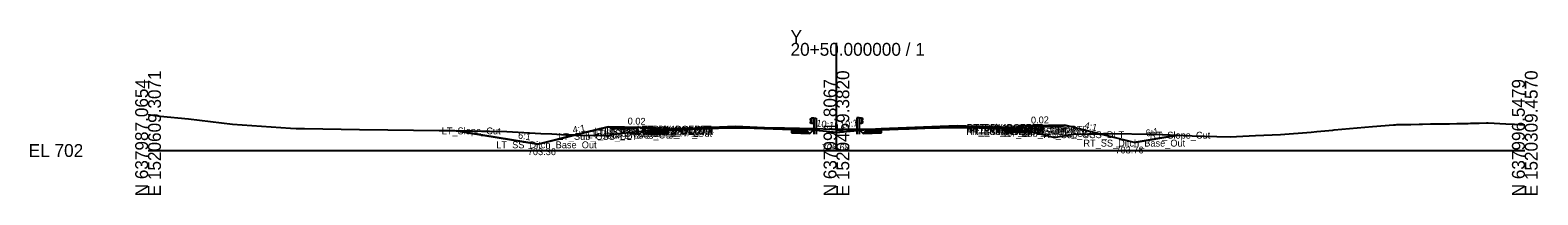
# Model space of a CAD drawing. Extents: x -26 to 303, y -10 to 5039.
# Drawn here: x -25.7 to 302.8, y 3990.3 to 4026.3 of the extents above; entities that cross this region are included whole.
import ezdxf

# ---------------------------------------------------------------- set-up
doc = ezdxf.new("R2010")
doc.units = 0
for name, color, linetype in [('Default', 7, 'Continuous'), ('Exist Cross Section Cell', 7, 'Continuous'), ('Exist XS Center Line Elevation Label', 7, 'Continuous'), ('Exist XS Ground Line', 7, 'Continuous'), ('Prop CMT Pvmt Course 1', 7, 'Continuous'), ('Prop CMT Pvmt Course 2', 7, 'Continuous'), ('Prop CMT Pvmt Course 3', 7, 'Continuous'), ('Prop CMT Pvmt Surface Shoulder', 7, 'Continuous'), ('Prop CMT Shld Paved Course 1', 7, 'Continuous'), ('Prop CMT Shld Paved Course 2', 7, 'Continuous'), ('Prop CMT Shld Paved Course 3', 7, 'Continuous'), ('Prop CMT Slope Grass', 7, 'Continuous'), ('Prop CMT Subgrade Earthwork', 7, 'Continuous'), ('Prop Conc 4in Sidewalk', 7, 'Continuous'), ('Prop XS Ditch Standard Text', 7, 'Continuous'), ('Prop XS Earthwork Shape', 7, 'Continuous'), ('Prop XS Side Slope Text', 7, 'Continuous'), ('Scratch_Level_0', 7, 'Continuous'), ('Typical Curb CELL', 7, 'Continuous'), ('Typical Guardrail CELL', 7, 'Continuous'), ('Typical Shoulder Slope Information CELL', 7, 'Continuous')]:
    doc.layers.add(name, color=color, linetype=linetype)

# ---------------------------------------------------------------- blocks, each defined once
blk = doc.blocks.new('2_6 CURB RIGHT')
at = {"layer": 'Typical Curb CELL'}
for p, q in [((0, -0.58), (0, 0)), ((0, 0), (1.75, -0.07)), ((2, 0.17), (2, 0.18)), ((2.5, 0.42), (2.24, 0.42)), ((2.31, 0.08), (2.33, -0.01)), ((2.46, 0.04), (2.31, 0.08)), ((2.33, -0.01), (2.46, 0.04)), ((2.5, -0.58), (2.5, 0.42)), ((2.5, -0.58), (0, -0.58)), ((0.26, -0.34), (0.35, -0.22)), ((0.38, -0.34), (0.26, -0.34)), ((0.35, -0.22), (0.38, -0.34)), ((1.03, -0.39), (1.09, -0.28)), ((1.19, -0.36), (1.03, -0.39)), ((1.09, -0.28), (1.19, -0.36)), ((1.51, -0.34), (1.6, -0.22)), ((1.63, -0.34), (1.51, -0.34)), ((1.6, -0.22), (1.63, -0.34)), ((2.27, -0.39), (2.34, -0.28)), ((2.44, -0.36), (2.27, -0.39)), ((2.34, -0.28), (2.44, -0.36))]:
    blk.add_line(p, q, dxfattribs=at)
for centre in [(2.27, 0.34), (2.43, 0.12), (2.49, 0.31), (0.01, -0.55), (0.02, -0.25), (0.03, -0.15), (0.07, -0.39), (0.09, -0.18), (0.17, -0.34), (0.2, -0.06), (0.22, -0.58), (0.3, -0.14), (0.34, -0.04), (0.38, -0.51), (0.49, -0.1), (0.52, -0.21), (0.59, -0.53), (0.67, -0.29), (0.69, -0.12), (0.7, -0.45), (0.71, -0.07), (0.76, -0.56), (0.79, -0.26), (0.93, -0.5), (0.97, -0.1), (1.09, -0.15), (1.11, -0.54), (1.26, -0.55), (1.27, -0.25), (1.28, -0.15), (1.32, -0.39), (1.34, -0.18), (1.42, -0.34), (1.45, -0.1), (1.47, -0.58), (1.54, -0.14), (1.63, -0.51), (1.74, -0.1), (1.77, -0.21), (1.84, -0.53), (1.92, -0.29), (1.94, -0.12), (1.95, -0.45), (1.96, -0.07), (2.01, -0.56), (2.04, -0.26), (2.18, -0.5), (2.22, -0.1), (2.34, -0.15), (2.35, -0.54)]:
    blk.add_circle(centre, 0.00802, dxfattribs=at)
for centre, start, end in [((1.76, 0.17), 267.6155, 0), ((2.24, 0.18), 90, 180)]:
    blk.add_arc(centre, 0.24, start, end, dxfattribs=at)

msp = doc.modelspace()

# ---------------------------------------------------------------- linework, layer by layer
at = {"layer": 'Exist Cross Section Cell'}
for p, q in [((150, 4000), (150, 4023.49)), ((0, 4000), (150, 4000)), ((150, 4000), (300, 4000))]:
    msp.add_line(p, q, dxfattribs=at)
at = {"layer": 'Exist XS Ground Line'}
msp.add_lwpolyline([(0, 4007.83), (2.65, 4007.47), (8.82, 4006.91), (18.4, 4005.77), (31.03, 4004.88), (32.29, 4004.83), (34.06, 4004.82), (46.09, 4004.6), (52.24, 4004.48), (63.44, 4004.38), (65.08, 4004.36), (65.85, 4004.35), (66.86, 4004.34), (78.21, 4004.14), (85.59, 4003.75), (87.97, 4003.66), (91.17, 4003.44), (94.16, 4003.35), (99.49, 4003.28), (100.04, 4003.28), (100.4, 4003.33), (102.19, 4003.61), (105.36, 4003.99), (106.12, 4004.06), (111.26, 4004.59), (112.28, 4004.58), (114.36, 4004.66), (116.71, 4004.72), (119.22, 4004.78), (121.72, 4004.85), (124.22, 4004.91), (125, 4004.94), (126.18, 4004.97), (126.72, 4004.97), (127.07, 4004.97), (129.21, 4004.97), (131.22, 4004.98), (131.7, 4004.98), (133.64, 4004.97), (134.21, 4004.97), (134.8, 4004.97), (136.73, 4004.96), (137.46, 4004.95), (138.15, 4004.95), (138.7, 4004.94), (141.96, 4004.87), (145.4, 4004.79), (148.89, 4004.69), (150, 4004.68), (152.34, 4004.66), (158.87, 4004.69), (160.57, 4004.68), (162.53, 4004.66), (164.26, 4004.71), (165.85, 4004.76), (166.76, 4004.78), (167.62, 4004.81), (169.25, 4004.87), (170.98, 4004.92), (171.73, 4004.94), (172.45, 4004.96), (174.53, 4005.04), (176.12, 4005.02), (176.73, 4005.02), (178.7, 4005.03), (179.22, 4005.03), (181.3, 4005.02), (181.73, 4005.02), (183.92, 4005.01), (184.26, 4005.01), (185.48, 4005.01), (186.05, 4005.01), (186.52, 4004.95), (188.98, 4004.75), (190.2, 4004.55), (192.8, 4004.02), (196.34, 4003.14), (197.52, 4002.85), (198.57, 4003.03), (201.65, 4003.56), (208.21, 4003.69), (209.22, 4003.69), (219.44, 4003.59), (225.64, 4003.27), (226.31, 4003.25), (227.52, 4003.22), (232.88, 4003.04), (235.76, 4002.98), (241.31, 4003.25), (246.78, 4003.52), (253.43, 4004.04), (254.69, 4004.15), (258.15, 4004.46), (258.45, 4004.49), (266.79, 4005.22), (271.42, 4005.63), (271.83, 4005.64), (272.14, 4005.65), (272.72, 4005.67), (274.38, 4005.7), (275.19, 4005.71), (277, 4005.75), (277.69, 4005.77), (279.42, 4005.8), (280.17, 4005.81), (281.85, 4005.83), (282.68, 4005.85), (283.56, 4005.86), (285.18, 4005.89), (286.14, 4005.91), (287.67, 4005.93), (288.17, 4005.95), (289.48, 4005.98), (290.02, 4005.98), (291.64, 4006.02), (292.01, 4006.01), (295.9, 4005.82), (297.7, 4005.74), (300, 4005.6)], dxfattribs=at)
at = {"layer": 'Prop CMT Pvmt Course 1'}
for points in [[(186.74, 4004.73), (186.74, 4004.98)], [(113.26, 4004.62), (113.26, 4004.37)], [(113.26, 4004.37), (113.27, 4004.37)], [(113.27, 4004.37), (113.27, 4004.62)], [(140.26, 4004.48), (140.26, 4004.73)], [(159.74, 4004.73), (159.74, 4004.48)], [(159.74, 4004.48), (159.75, 4004.48)], [(159.75, 4004.48), (159.75, 4004.73)], [(159.75, 4004.48), (159.75, 4004.73)]]:
    msp.add_lwpolyline(points, dxfattribs=at)
at = {"layer": 'Prop CMT Pvmt Course 2'}
for points in [[(113.27, 4004.37), (113.26, 4004.37)], [(113.26, 4004.37), (113.26, 4004.12)], [(113.26, 4004.12), (113.27, 4004.12)], [(113.27, 4004.12), (113.27, 4004.37)], [(140.26, 4004.23), (140.26, 4004.48)], [(159.75, 4004.48), (159.74, 4004.48)], [(159.74, 4004.48), (159.74, 4004.23)], [(159.74, 4004.23), (159.75, 4004.23)], [(159.75, 4004.23), (159.75, 4004.48)], [(159.75, 4004.23), (159.75, 4004.48)]]:
    msp.add_lwpolyline(points, dxfattribs=at)
at = {"layer": 'Prop CMT Pvmt Course 3'}
for points in [[(113.27, 4004.12), (113.26, 4004.12)], [(113.26, 4004.12), (113.26, 4003.75)], [(113.26, 4003.75), (113.27, 4003.75)], [(113.27, 4003.75), (113.27, 4004.12)], [(140.26, 4003.86), (140.26, 4004.23)], [(140.27, 4003.86), (140.26, 4003.86)], [(159.75, 4004.23), (159.74, 4004.23)], [(159.74, 4004.23), (159.74, 4003.86)], [(159.74, 4003.86), (159.75, 4003.86)], [(159.74, 4003.86), (159.75, 4003.86)], [(159.75, 4003.86), (159.75, 4004.23)], [(159.75, 4003.86), (159.75, 4004.23)]]:
    msp.add_lwpolyline(points, dxfattribs=at)
at = {"layer": 'Prop CMT Pvmt Surface Shoulder'}
for points in [[(128, 4005.22), (112.26, 4004.57)], [(128, 4005.22), (143.26, 4004.61)], [(176.31, 4005.39), (156.75, 4004.61)], [(176.31, 4005.39), (187.75, 4004.94)]]:
    msp.add_lwpolyline(points, dxfattribs=at)
at = {"layer": 'Prop CMT Shld Paved Course 1'}
for p, q in [((128, 4004.97), (113.27, 4004.37)), ((176.3, 4005.14), (187.74, 4004.69))]:
    msp.add_line(p, q, dxfattribs=at)
for points in [[(140.26, 4004.48), (128, 4004.97)], [(159.77, 4004.48), (176.3, 4005.14)], [(112.26, 4004.33), (113.27, 4004.37)], [(113.26, 4004.37), (113.26, 4004.62)], [(159.74, 4004.48), (159.74, 4004.73)], [(187.75, 4004.69), (186.74, 4004.73)]]:
    msp.add_lwpolyline(points, dxfattribs=at)
at = {"layer": 'Prop CMT Shld Paved Course 2'}
for p, q in [((143.78, 4004.09), (143.52, 4004.35)), ((156.23, 4004.09), (156.49, 4004.35))]:
    msp.add_line(p, q, dxfattribs=at)
for points in [[(113.27, 4004.37), (112.26, 4004.33)], [(112.26, 4004.08), (113.27, 4004.12)], [(113.26, 4004.12), (113.26, 4004.37)], [(140.26, 4004.48), (143.52, 4004.35)], [(143.78, 4004.09), (140.26, 4004.23)], [(156.23, 4004.09), (159.75, 4004.23)], [(159.75, 4004.48), (156.49, 4004.35)], [(157.24, 4004.13), (159.76, 4004.23)], [(159.74, 4004.23), (159.74, 4004.48)], [(186.74, 4004.73), (187.75, 4004.69)], [(187.75, 4004.44), (186.74, 4004.48)]]:
    msp.add_lwpolyline(points, dxfattribs=at)
at = {"layer": 'Prop CMT Shld Paved Course 3'}
for p, q in [((109.26, 4004), (108.83, 4003.57)), ((109.76, 4004), (109.26, 4004)), ((144.17, 4003.7), (143.78, 4004.09)), ((155.84, 4003.7), (156.23, 4004.09)), ((190.25, 4004.35), (190.75, 4004.35)), ((190.75, 4004.35), (191.18, 4003.92))]:
    msp.add_line(p, q, dxfattribs=at)
for points in [[(108.83, 4003.57), (113.27, 4003.75)], [(113.27, 4004.12), (112.26, 4004.08)], [(113.26, 4003.75), (113.26, 4004.12)], [(140.26, 4004.23), (143.78, 4004.09)], [(144.17, 4003.7), (140.26, 4003.86)], [(155.84, 4003.7), (159.75, 4003.86)], [(159.75, 4004.23), (156.23, 4004.09)], [(159.74, 4003.86), (159.74, 4004.23)], [(186.74, 4004.48), (187.75, 4004.44)], [(191.18, 4003.92), (186.74, 4004.1)]]:
    msp.add_lwpolyline(points, dxfattribs=at)
at = {"layer": 'Prop CMT Slope Grass'}
for p, q in [((84.98, 4001.36), (100.26, 4005.18)), ((100.26, 4005.18), (109.76, 4004.99)), ((199.75, 4005.54), (190.25, 4005.35)), ((214.9, 4001.75), (199.75, 4005.54)), ((67.13, 4004.33), (84.98, 4001.36)), ((150.01, 4003.94), (143.26, 4004.61)), ((150.01, 4003.94), (156.75, 4004.61))]:
    msp.add_line(p, q, dxfattribs=at)
msp.add_lwpolyline([(214.9, 4001.75), (224.38, 4003.34)], dxfattribs=at)
at = {"layer": 'Prop CMT Subgrade Earthwork'}
for p, q in [((108.83, 4003.57), (107.36, 4005.05)), ((186.74, 4004.1), (186.74, 4004.98)), ((191.18, 4003.92), (192.65, 4005.4)), ((113.27, 4003.75), (113.27, 4004.62)), ((140.26, 4004.73), (140.26, 4003.86)), ((159.75, 4004.73), (159.75, 4003.86))]:
    msp.add_line(p, q, dxfattribs=at)
for points in [[(113.27, 4003.75), (108.83, 4003.57)], [(140.26, 4004.73), (140.26, 4003.86), (140.27, 4003.86)], [(140.26, 4003.86), (144.17, 4003.7)], [(144.17, 4003.7), (144.92, 4004.45)], [(155.84, 4003.7), (155.09, 4004.45)], [(159.75, 4003.86), (155.84, 4003.7)], [(186.74, 4004.1), (191.18, 4003.92)]]:
    msp.add_lwpolyline(points, dxfattribs=at)
at = {"layer": 'Prop Conc 4in Sidewalk'}
for p, q in [((100.76, 4005.17), (100.76, 4004.84)), ((100.76, 4004.84), (105.76, 4004.74)), ((105.76, 4005.07), (105.76, 4004.74)), ((194.25, 4005.43), (194.25, 4005.1)), ((199.25, 4005.2), (194.25, 4005.1)), ((199.25, 4005.53), (199.25, 4005.2))]:
    msp.add_line(p, q, dxfattribs=at)
at = {"layer": 'Prop XS Earthwork Shape'}
for points in [[(100.04, 4003.28), (100.4, 4003.33), (102.19, 4003.61), (105.36, 4003.99), (106.12, 4004.06), (108.13, 4004.27), (107.36, 4005.04), (100.26, 4005.18), (93.08, 4003.39), (94.16, 4003.35), (99.49, 4003.28)], [(125, 4004.94), (126.18, 4004.97), (126.72, 4004.97), (127.07, 4004.97), (129.21, 4004.97), (131.22, 4004.98), (131.7, 4004.98), (133.64, 4004.97), (134.21, 4004.97), (134.3, 4004.97), (128, 4005.22), (114.36, 4004.66), (116.71, 4004.72), (119.22, 4004.78), (121.72, 4004.85), (124.22, 4004.91)], [(134.8, 4004.97), (136.73, 4004.96), (137.46, 4004.95), (138.15, 4004.95), (138.7, 4004.94), (141.96, 4004.87), (145.4, 4004.79), (148.89, 4004.69), (150, 4004.68), (152.34, 4004.66), (158.78, 4004.69), (156.75, 4004.61), (155.09, 4004.45), (150.01, 4003.94), (144.92, 4004.45), (143.26, 4004.61), (140.26, 4004.73), (134.3, 4004.97)], [(169.25, 4004.87), (170.98, 4004.92), (171.73, 4004.94), (172.45, 4004.96), (174.53, 4005.04), (176.12, 4005.02), (176.73, 4005.02), (178.7, 4005.03), (179.22, 4005.03), (181.3, 4005.02), (181.73, 4005.02), (183.92, 4005.01), (184.26, 4005.01), (185.48, 4005.01), (186.01, 4005.01), (176.31, 4005.39), (159.75, 4004.73), (159.75, 4004.69), (160.57, 4004.68), (162.53, 4004.66), (164.26, 4004.71), (165.85, 4004.76), (166.76, 4004.78), (167.62, 4004.81)], [(186.07, 4005), (186.74, 4004.98), (186.74, 4004.94), (186.52, 4004.95)], [(191.18, 4003.92), (191.53, 4004.28), (190.2, 4004.55), (188.98, 4004.75), (186.74, 4004.94), (186.74, 4004.1)], [(191.53, 4004.28), (192.8, 4004.02), (196.34, 4003.14), (197.52, 4002.85), (198.57, 4003.03), (201.65, 4003.56), (207.25, 4003.67), (199.75, 4005.54), (192.65, 4005.4)], [(91.17, 4003.44), (93.08, 4003.39), (84.98, 4001.36), (67.13, 4004.33), (78.21, 4004.14), (85.59, 4003.75), (87.97, 4003.66)], [(108.83, 4003.57), (108.13, 4004.27), (111.26, 4004.59), (112.21, 4004.58), (112.26, 4004.57), (113.27, 4004.62), (113.27, 4003.75)], [(112.21, 4004.58), (112.26, 4004.57), (113.27, 4004.62), (112.28, 4004.58)], [(140.27, 4003.86), (144.17, 4003.7), (144.92, 4004.45), (143.26, 4004.61), (140.26, 4004.73)], [(159.75, 4004.69), (159.75, 4003.86), (155.84, 4003.7), (155.09, 4004.45), (156.75, 4004.61), (158.78, 4004.69), (158.87, 4004.69)], [(207.25, 4003.67), (208.21, 4003.69), (209.22, 4003.69), (219.44, 4003.59), (224.38, 4003.34), (214.9, 4001.75)]]:
    msp.add_lwpolyline(points, close=True, dxfattribs=at)
at = {"layer": 'Typical Guardrail CELL'}
for p, q in [((144.57, 4007.06), (144.28, 4006.85)), ((144.57, 4006.52), (144.28, 4006.73)), ((144.57, 4006.43), (144.28, 4006.23)), ((144.57, 4005.9), (144.28, 4006.1)), ((145.07, 4007.06), (144.57, 4007.06)), ((144.57, 4007.06), (144.57, 4005.9)), ((144.57, 4006.48), (144.57, 4006.52)), ((144.57, 4006.48), (144.57, 4006.43)), ((145.07, 4005.9), (144.57, 4005.9)), ((145.07, 4007.06), (145.07, 4004.57)), ((145.07, 4007.06), (145.57, 4007.06)), ((145.57, 4007.06), (145.57, 4004.57)), ((154.93, 4007.1), (154.43, 4007.1)), ((154.43, 4007.1), (154.43, 4004.61)), ((154.93, 4007.1), (154.93, 4004.61)), ((154.93, 4007.1), (155.43, 4007.1)), ((154.93, 4005.94), (155.43, 4005.94)), ((155.43, 4007.1), (155.43, 4005.94)), ((155.43, 4007.1), (155.72, 4006.89)), ((155.43, 4006.56), (155.72, 4006.77)), ((155.43, 4006.52), (155.43, 4006.56)), ((155.43, 4006.52), (155.43, 4006.47)), ((155.43, 4006.47), (155.72, 4006.27)), ((155.43, 4005.94), (155.72, 4006.14)), ((145.07, 4004.57), (145.57, 4004.57)), ((145.07, 4004.57), (145.07, 4003.56)), ((145.57, 4004.57), (145.57, 4003.56)), ((154.93, 4004.61), (154.43, 4004.61)), ((154.43, 4004.61), (154.43, 4003.6)), ((154.93, 4004.61), (154.93, 4003.6))]:
    msp.add_line(p, q, dxfattribs=at)
for centre, start, end in [((144.33, 4006.79), 125.003, 235.0112), ((144.33, 4006.16), 125.0059, 235.0366), ((155.67, 4006.83), 304.9888, 54.997), ((155.67, 4006.2), 304.9634, 54.9941)]:
    msp.add_arc(centre, 0.0776, start, end, dxfattribs=at)

# ---------------------------------------------------------------- block references
at = {"layer": 'Prop CMT Slope Grass', "yscale": -1, "rotation": 180}
msp.add_blockref('2_6 CURB RIGHT', (112.26, 4004.57), dxfattribs=at)
at = {"layer": 'Prop CMT Slope Grass'}
msp.add_blockref('2_6 CURB RIGHT', (187.75, 4004.94), dxfattribs=at)

# ---------------------------------------------------------------- texts
at = {"layer": 'Default'}
msp.add_text('-', height=0.0001, dxfattribs=at).set_placement((0, 4000))
at = {"layer": 'Exist Cross Section Cell'}
for s, p in [('Y', (140, 4023.49)), ('20+50.000000 / 1', (140, 4020.69)), ('EL 702', (-26, 3998.6))]:
    msp.add_text(s, height=2.8, dxfattribs=at).set_placement(p)
for s, p in [('N 637987.0654', (0, 3990)), ('E 1520609.3071', (2.8, 3990)), ('N 637991.8067', (150, 3990)), ('E 1520459.3820', (152.8, 3990)), ('N 637996.5479', (300, 3990)), ('E 1520309.4570', (302.8, 3990))]:
    msp.add_text(s, height=2.8, rotation=90, dxfattribs=at).set_placement(p)
at = {"layer": 'Exist XS Center Line Elevation Label'}
msp.add_text('706.68', height=1.5, dxfattribs=at).set_placement((146.79, 3999.93))
at = {"layer": 'Prop XS Ditch Standard Text'}
for s, p in [('703.36', (82.74, 3998.99)), ('703.76', (210.78, 3999.36))]:
    msp.add_text(s, height=1.5, dxfattribs=at).set_placement(p)
at = {"layer": 'Prop XS Side Slope Text'}
for s, rotation, p in [('4:1', 9.4623, (92.64, 4003.75)), ('10:1', 350.5377, (145.52, 4005.31)), ('10:1', 9.4623, (150.95, 4004.77)), ('4:1', 346.7942, (203.91, 4004.84)), ('6:1', 9.4809, (217.54, 4003.03)), ('6:1', 350.5191, (80.54, 4002.65))]:
    msp.add_text(s, height=1.5, rotation=rotation, dxfattribs=at).set_placement(p)
at = {"layer": 'Scratch_Level_0'}
for s, p in [('LT_Slope_Cut', (63.99, 4003.53)), ('LT_GS_OS_CTL', (97.19, 4003.49)), ('LT_PS2_OEOP', (99.41, 4003.31)), ('LT_PS1_OEOP', (99.85, 4003.57)), ('LT_PV2_PGL_Out', (106.36, 4003.64)), ('LT_PV3_PGL_Out', (106.36, 4003.39)), ('LT_Sub_Out_DLT', (106.49, 4003.89)), ('LT_PV1_PGL_Out', (106.54, 4003.89)), ('LT_PV2_OEOT', (107.61, 4003.64)), ('LT_PV3_OEOT', (107.61, 4003.39)), ('LT_PV1_OEOT', (107.79, 4003.89)), ('RT_PV2_PGL_Out', (178.27, 4004.01)), ('RT_PV3_PGL_Out', (178.27, 4003.76)), ('RT_Sub_PGL_Out', (178.31, 4003.38)), ('RT_Sub_Out_DLT', (178.37, 4004.26)), ('RT_PV1_PGL_Out', (178.45, 4004.26)), ('RT_PV2_OEOT', (179.54, 4004.01)), ('RT_PV3_OEOT', (179.54, 4003.76)), ('RT_Sub_OEOT', (179.57, 4003.38)), ('RT_PV1_OEOT', (179.72, 4004.26)), ('RT_PS3_Shelf_Out', (186.93, 4003.4)), ('RT_PS1_OEOP', (187.78, 4003.94)), ('RT_PS2_OEOP', (187.86, 4003.68)), ('RT_PS3_OEOP', (188.12, 4003.42)), ('RT_GS_OS_CTL', (189.12, 4003.86)), ('LT_SS_Ditch_Base_Out', (75.88, 4000.49)), ('LT_Sub_OSS_DLT', (89.35, 4002.33)), ('LT_Sub_Trench_Out', (95.74, 4002.63)), ('LT_PS3_Shelf_Out', (96.95, 4003.02)), ('LT_PS3_OEOP', (99.15, 4003.04)), ('LT_Sub_PGL_Out', (106.4, 4003.01)), ('LT_Sub_OEOT', (107.64, 4003.01)), ('RT_Sub_Trench_Out', (186.5, 4003)), ('RT_Sub_OSS_DLT', (195.1, 4002.7)), ('RT_SS_Ditch_Base_Out', (203.81, 4000.86)), ('RT_Slope_Cut', (218.3, 4002.59))]:
    msp.add_text(s, height=1.5, dxfattribs=at).set_placement(p)
at = {"layer": 'Typical Shoulder Slope Information CELL'}
for rotation, p in [(358.8597, (104.49, 4005.69)), (1.1403, (192.4, 4005.88))]:
    msp.add_text('0.02', height=1.5, rotation=rotation, dxfattribs=at).set_placement(p)

doc.saveas('drawing.dxf')
